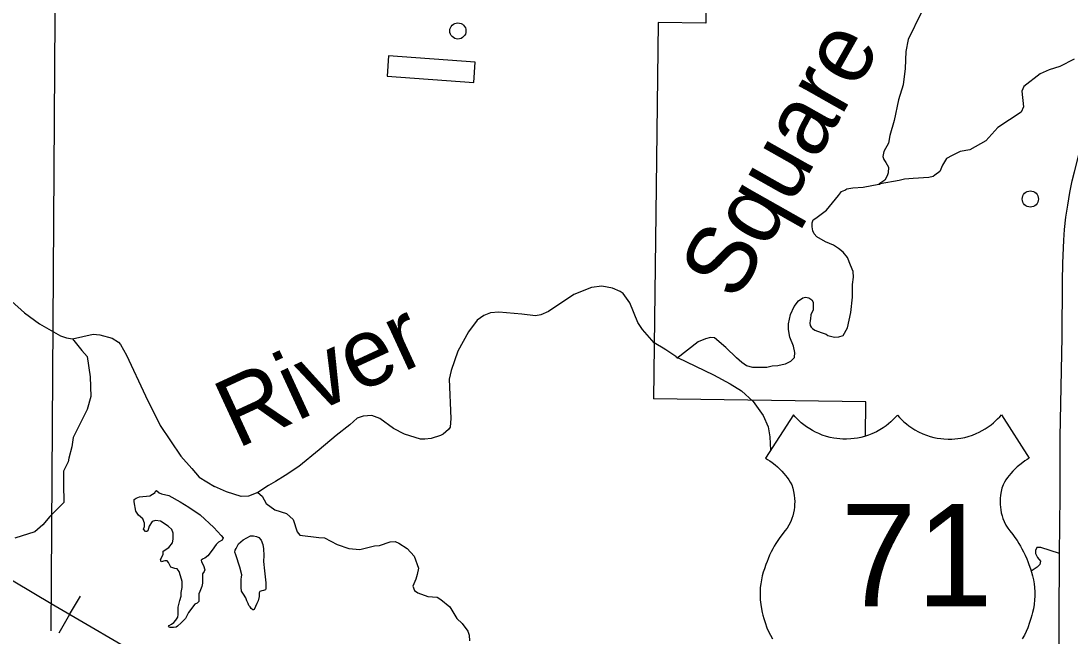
# Model space of a CAD drawing. Extents: x 1382482 to 1385815, y 1168351 to 1170484.
# Drawn here: x 1384071.2 to 1384330.9, y 1169323.8 to 1169475.9 of the extents above; entities that cross this region are included whole.
import ezdxf

# ---------------------------------------------------------------- set-up
doc = ezdxf.new("R2010")
doc.units = 0
for name, color, linetype in [('15', 7, 'Continuous'), ('22', 7, 'Continuous'), ('35', 7, 'Continuous'), ('4', 7, 'Continuous'), ('57', 7, 'Continuous'), ('6', 7, 'Continuous'), ('Default', 7, 'Continuous')]:
    doc.layers.add(name, color=color, linetype=linetype)

msp = doc.modelspace()

# ---------------------------------------------------------------- linework, layer by layer
at = {"layer": '15'}
msp.add_lwpolyline([(1384338.14, 1169311.22), (1384328.14, 1169311.27), (1384328.32, 1169344.04), (1384328.45, 1169358.54), (1384328.5, 1169373.03), (1384328.95, 1169397.67), (1384329.04, 1169411.52), (1384329.08, 1169416.04), (1384329.38, 1169421.73), (1384329.53, 1169424.34), (1384329.9, 1169427.4), (1384330.37, 1169430.41), (1384330.88, 1169433.52), (1384331.42, 1169436.43), (1384332, 1169438.62), (1384333.21, 1169443.46), (1384334.5, 1169447.58), (1384335.93, 1169451.66), (1384338.18, 1169457.24), (1384342.61, 1169467.31), (1384344.9, 1169472.5)], dxfattribs=at)
at = {"layer": '22'}
for points in [[(1384288.16, 1169378.43), (1384287.63, 1169377.84), (1384287.13, 1169377.32), (1384286.56, 1169376.79), (1384285.94, 1169376.26), (1384285.35, 1169375.8), (1384284.62, 1169375.29), (1384283.85, 1169374.81), (1384282.97, 1169374.32), (1384281.85, 1169373.8), (1384280.99, 1169373.47), (1384280.01, 1169373.15), (1384279.13, 1169372.92), (1384278.31, 1169372.75), (1384277.44, 1169372.62), (1384276.65, 1169372.54), (1384275.56, 1169372.49), (1384274.67, 1169372.5), (1384273.9, 1169372.54), (1384273.17, 1169372.62), (1384272.43, 1169372.73), (1384271.49, 1169372.92), (1384270.63, 1169373.15), (1384269.58, 1169373.49), (1384268.69, 1169373.84), (1384267.88, 1169374.22), (1384267.14, 1169374.6), (1384266.45, 1169375.01), (1384265.68, 1169375.51), (1384264.98, 1169376.02), (1384264.38, 1169376.52), (1384263.87, 1169376.97), (1384263.35, 1169377.47), (1384262.84, 1169378.01), (1384262.42, 1169378.49), (1384255.5, 1169367.78), (1384255.99, 1169367.48), (1384256.58, 1169367.1), (1384257.14, 1169366.7), (1384257.88, 1169366.12), (1384258.48, 1169365.61), (1384259.01, 1169365.12), (1384259.54, 1169364.58), (1384260.09, 1169363.96), (1384260.48, 1169363.49), (1384260.87, 1169362.99), (1384261.27, 1169362.44), (1384261.65, 1169361.86), (1384262, 1169361.18), (1384262.27, 1169360.34), (1384262.48, 1169359.52), (1384262.63, 1169358.63), (1384262.71, 1169357.81), (1384262.74, 1169357.02), (1384262.72, 1169356.28), (1384262.67, 1169355.68), (1384262.57, 1169354.95), (1384262.44, 1169354.27), (1384262.25, 1169353.53), (1384262.04, 1169352.87), (1384261.75, 1169352.14), (1384261.3, 1169351.2), (1384260.84, 1169350.46), (1384260.28, 1169349.79), (1384259.61, 1169348.92), (1384259.06, 1169348.16), (1384258.54, 1169347.39), (1384258.07, 1169346.65), (1384257.68, 1169345.97), (1384257.33, 1169345.35), (1384256.94, 1169344.6), (1384256.52, 1169343.73), (1384256.14, 1169342.87), (1384255.89, 1169342.23), (1384255.58, 1169341.42), (1384255.24, 1169340.42), (1384254.97, 1169339.59), (1384254.72, 1169338.69), (1384254.49, 1169337.64), (1384254.34, 1169336.7), (1384254.22, 1169335.73), (1384254.16, 1169334.66), (1384254.16, 1169333.66), (1384254.2, 1169332.68), (1384254.32, 1169331.53), (1384254.5, 1169330.45), (1384254.68, 1169329.62), (1384254.87, 1169328.9), (1384255.1, 1169328.08), (1384255.42, 1169327.07), (1384255.88, 1169325.83), (1384256.27, 1169324.92), (1384256.73, 1169323.99), (1384257.23, 1169323.08)], [(1384288.16, 1169378.43), (1384288.69, 1169377.84), (1384289.19, 1169377.32), (1384289.76, 1169376.79), (1384290.38, 1169376.26), (1384290.98, 1169375.8), (1384291.7, 1169375.29), (1384292.47, 1169374.81), (1384293.36, 1169374.32), (1384294.48, 1169373.8), (1384295.34, 1169373.47), (1384296.31, 1169373.15), (1384297.2, 1169372.92), (1384298.02, 1169372.75), (1384298.88, 1169372.62), (1384299.67, 1169372.54), (1384300.76, 1169372.49), (1384301.65, 1169372.5), (1384302.42, 1169372.54), (1384303.15, 1169372.62), (1384303.89, 1169372.73), (1384304.83, 1169372.92), (1384305.69, 1169373.15), (1384306.74, 1169373.49), (1384307.63, 1169373.84), (1384308.44, 1169374.22), (1384309.19, 1169374.6), (1384309.87, 1169375.01), (1384310.64, 1169375.51), (1384311.34, 1169376.02), (1384311.94, 1169376.52), (1384312.45, 1169376.97), (1384312.97, 1169377.47), (1384313.49, 1169378.01), (1384313.9, 1169378.49), (1384320.82, 1169367.78), (1384320.33, 1169367.48), (1384319.74, 1169367.1), (1384319.18, 1169366.7), (1384318.44, 1169366.12), (1384317.84, 1169365.61), (1384317.32, 1169365.12), (1384316.78, 1169364.58), (1384316.23, 1169363.96), (1384315.84, 1169363.49), (1384315.45, 1169362.99), (1384315.05, 1169362.44), (1384314.67, 1169361.86), (1384314.32, 1169361.18), (1384314.05, 1169360.34), (1384313.84, 1169359.52), (1384313.69, 1169358.63), (1384313.61, 1169357.81), (1384313.58, 1169357.02), (1384313.6, 1169356.28), (1384313.65, 1169355.68), (1384313.75, 1169354.95), (1384313.88, 1169354.27), (1384314.07, 1169353.53), (1384314.28, 1169352.87), (1384314.57, 1169352.14), (1384315.02, 1169351.2), (1384315.48, 1169350.46), (1384316.04, 1169349.79), (1384316.71, 1169348.92), (1384317.26, 1169348.16), (1384317.78, 1169347.39), (1384318.25, 1169346.65), (1384318.64, 1169345.97), (1384318.99, 1169345.35), (1384319.38, 1169344.6), (1384319.8, 1169343.73), (1384320.18, 1169342.87), (1384320.44, 1169342.23), (1384320.74, 1169341.42), (1384321.08, 1169340.42), (1384321.35, 1169339.59), (1384321.6, 1169338.69), (1384321.83, 1169337.64), (1384321.99, 1169336.7), (1384322.1, 1169335.73), (1384322.16, 1169334.66), (1384322.17, 1169333.66), (1384322.12, 1169332.68), (1384322, 1169331.53), (1384321.82, 1169330.45), (1384321.64, 1169329.62), (1384321.46, 1169328.9), (1384321.22, 1169328.08), (1384320.9, 1169327.07), (1384320.44, 1169325.83), (1384320.05, 1169324.92), (1384319.59, 1169323.99), (1384319.09, 1169323.08)]]:
    msp.add_lwpolyline(points, dxfattribs=at)
at = {"layer": '35'}
for p, q in [((1384262.73, 1169392.71), (1384262.73, 1169392.71)), ((1384263.22, 1169393.72), (1384263.22, 1169393.72))]:
    msp.add_line(p, q, dxfattribs=at)
for points in [[(1384294.03, 1169477.94), (1384290.84, 1169471.32), (1384290.27, 1169468.35), (1384290.05, 1169464.19), (1384289.6, 1169460.15), (1384288.43, 1169456.47), (1384287.38, 1169451.3), (1384286.29, 1169447.62), (1384285.99, 1169445.7), (1384284.79, 1169443.67), (1384284.53, 1169442.42), (1384284.82, 1169441.66), (1384285.33, 1169440.92), (1384285.93, 1169439.73)], [(1384331.95, 1169466.52), (1384328.35, 1169464.72), (1384325.72, 1169463.82), (1384323.47, 1169462.87), (1384319.5, 1169459.76), (1384318.97, 1169458.56), (1384319.35, 1169454.74), (1384318.82, 1169453.39), (1384313.03, 1169449.56), (1384310.03, 1169446.32), (1384306.09, 1169444.1), (1384303.7, 1169443.66), (1384301.71, 1169442.68), (1384300.32, 1169441.89), (1384299.31, 1169440.28), (1384298.63, 1169438.67), (1384297.47, 1169437.77), (1384297.02, 1169437.5), (1384295.97, 1169437.2), (1384292.07, 1169436.98), (1384289.91, 1169436.81), (1384288.59, 1169436.48), (1384283.89, 1169435.61)], [(1384285.93, 1169439.73), (1384285.85, 1169438.38), (1384285.66, 1169437.65), (1384285.04, 1169436.57), (1384283.58, 1169435.53)], [(1384262.73, 1169392.71), (1384262.76, 1169393.95), (1384262.41, 1169395.49), (1384261.52, 1169397.73), (1384261.18, 1169399.62), (1384261.18, 1169401.01), (1384261.68, 1169403.28), (1384262.64, 1169405.28), (1384263.72, 1169406.67), (1384264.76, 1169407.44), (1384265.45, 1169407.63), (1384266.26, 1169407.44), (1384266.99, 1169406.98), (1384267.34, 1169406.36), (1384267.34, 1169405.67), (1384267.3, 1169404.51), (1384266.76, 1169403.24), (1384266.65, 1169402.28), (1384266.57, 1169401.81), (1384266.45, 1169401.16), (1384266.57, 1169400.58), (1384266.8, 1169400.2), (1384267.15, 1169399.85), (1384267.69, 1169399.46), (1384269.3, 1169398.85), (1384270.5, 1169398.42), (1384270.96, 1169398.12), (1384272.58, 1169397.73), (1384273.7, 1169397.77), (1384274.74, 1169398.08), (1384275.78, 1169400), (1384276.66, 1169403.78), (1384277.01, 1169407.6), (1384277.09, 1169410.72), (1384277.28, 1169412.53), (1384277.2, 1169413.92), (1384276.59, 1169415.49), (1384275.78, 1169417.38), (1384274.74, 1169418.73), (1384273.62, 1169419.61), (1384272.35, 1169420.46), (1384270.34, 1169421.31), (1384268.23, 1169422.5), (1384267.57, 1169423.27), (1384267.22, 1169423.99), (1384267.03, 1169424.99), (1384267.07, 1169426.03), (1384267.34, 1169426.76), (1384267.99, 1169427.19), (1384270.61, 1169429.11), (1384273.62, 1169432.73), (1384274.35, 1169433.74), (1384275.12, 1169434.08), (1384275.68, 1169434.45), (1384277.11, 1169434.68), (1384279.73, 1169434.84), (1384283.58, 1169435.53), (1384283.86, 1169435.56), (1384283.89, 1169435.61)], [(1384042.2, 1169423.59), (1384050.89, 1169420.16), (1384057.39, 1169417.61), (1384059.78, 1169415.91), (1384063.8, 1169412.46), (1384068.87, 1169406.62), (1384072.09, 1169403.76), (1384075.79, 1169400.99), (1384080.97, 1169398.03), (1384082.46, 1169397.55), (1384083.93, 1169397.33), (1384089.09, 1169398.43), (1384090.76, 1169398.29), (1384093.8, 1169397.49), (1384095.31, 1169396.46), (1384095.87, 1169395.89), (1384097.31, 1169393.27), (1384102.03, 1169383.17), (1384105.64, 1169375.88), (1384110.75, 1169368.27), (1384113.52, 1169365.19), (1384115.33, 1169363.09), (1384119.13, 1169360.72)], [(1384217.61, 1169409.87), (1384214.97, 1169410.33), (1384212.46, 1169410.03), (1384208.09, 1169408.28), (1384201.81, 1169404.02), (1384199.93, 1169403.24), (1384198.54, 1169402.99), (1384195.21, 1169403.43), (1384189.46, 1169403.91), (1384187.4, 1169403.72), (1384185.76, 1169403.05), (1384184.12, 1169401.95), (1384181.98, 1169399.04), (1384179.33, 1169394.28), (1384177.7, 1169389.42), (1384177.19, 1169387.28), (1384177.6, 1169377.56), (1384177.46, 1169375.44), (1384177, 1169374.89), (1384175.75, 1169373.71), (1384175.05, 1169373.34), (1384172.77, 1169372.61), (1384171.19, 1169372.49), (1384170.11, 1169372.46), (1384166.15, 1169373.67), (1384163.44, 1169375.15), (1384160.06, 1169377.6), (1384158.05, 1169378.32), (1384155.93, 1169378.15), (1384154.46, 1169377.66), (1384152.65, 1169376.03), (1384149.27, 1169373.38), (1384144.99, 1169369.86), (1384139.99, 1169365.71), (1384136.6, 1169363.5), (1384134.21, 1169361.96), (1384132.47, 1169360.99), (1384129.87, 1169359.29), (1384127.57, 1169358.34), (1384125.73, 1169358.28), (1384122.1, 1169359.46), (1384119.13, 1169360.72)], [(1384233.32, 1169392.92), (1384230.58, 1169394.77), (1384227.94, 1169396.27), (1384225.05, 1169399.61), (1384223.88, 1169401.32), (1384221.9, 1169406.18), (1384220.25, 1169408.53), (1384219.57, 1169409.04), (1384217.61, 1169409.87)], [(1384083.93, 1169397.33), (1384086.31, 1169394.39), (1384087.56, 1169392.96), (1384088.33, 1169387.9), (1384088.48, 1169383), (1384087.59, 1169379.78), (1384084.09, 1169372.86), (1384083.83, 1169370.54), (1384083.05, 1169367.77), (1384082.91, 1169366.86), (1384081.77, 1169364.57), (1384081.75, 1169361.35), (1384081.82, 1169356.82), (1384079.58, 1169354.61), (1384078.36, 1169353.31), (1384076.6, 1169351.24), (1384074.61, 1169349.52), (1384069.68, 1169347.99)], [(1384262.73, 1169392.71), (1384261.73, 1169391.67), (1384260.38, 1169391.02), (1384258.59, 1169390.65), (1384257.19, 1169390.55), (1384255.88, 1169390.23), (1384252.39, 1169390.18), (1384250.85, 1169390.61), (1384249.69, 1169391.46), (1384248.35, 1169392.57), (1384245.69, 1169395.12), (1384242.91, 1169397.51), (1384241.91, 1169397.66), (1384240.65, 1169397.28), (1384238.86, 1169396.53), (1384233.59, 1169392.39)], [(1384230.58, 1169394.77), (1384230.78, 1169394.63)], [(1384233.32, 1169392.92), (1384233.71, 1169392.69), (1384242.61, 1169388.41), (1384246.77, 1169386.18), (1384249.54, 1169384.4), (1384252.47, 1169381.82), (1384254.9, 1169378.35), (1384256.2, 1169375.49), (1384256.55, 1169373.04), (1384256.79, 1169369.78)], [(1384110.88, 1169334.52), (1384111.1, 1169335.78), (1384111.1, 1169337.25), (1384110.66, 1169338.65), (1384110.36, 1169339.76), (1384109.85, 1169340.42), (1384109.26, 1169340.5), (1384108.3, 1169340.79), (1384107.71, 1169341.97), (1384107.41, 1169342.34), (1384106.82, 1169342.34), (1384105.87, 1169342.12), (1384105.72, 1169342.71), (1384106.38, 1169343.96), (1384106.38, 1169344.77), (1384107.78, 1169345.66), (1384108.74, 1169346.84), (1384108.89, 1169347.72), (1384108.89, 1169349.2), (1384108.52, 1169350.15), (1384107.64, 1169350.97), (1384105.72, 1169352.15), (1384104.5, 1169352.33), (1384103.66, 1169352.07), (1384102.92, 1169350.97), (1384102.62, 1169349.79), (1384102.33, 1169349.64), (1384102.03, 1169349.64), (1384101.52, 1169350.23), (1384101.81, 1169350.89), (1384101.81, 1169351.7), (1384101.37, 1169352.73), (1384100.26, 1169353.69), (1384099.68, 1169354.65), (1384099.23, 1169356.97), (1384099.23, 1169357.56), (1384099.71, 1169357.9), (1384100.56, 1169358.19), (1384103.07, 1169358.49), (1384104.39, 1169359.3), (1384104.54, 1169359.59), (1384104.76, 1169359.74), (1384105.42, 1169359.19), (1384106.01, 1169358.93), (1384107.78, 1169358.56)], [(1384107.78, 1169358.56), (1384110.61, 1169356.98), (1384112.79, 1169355.66), (1384115.59, 1169353.74), (1384118.94, 1169350.61), (1384120.75, 1169348.65), (1384121.23, 1169348.03), (1384121.04, 1169347.51), (1384120.12, 1169346.96), (1384119.53, 1169346.44), (1384118.54, 1169345), (1384117.47, 1169343.64), (1384116.69, 1169343.01), (1384116.33, 1169342.86), (1384115.85, 1169342.53), (1384115.92, 1169342.16), (1384116.36, 1169341.2), (1384116.69, 1169340.14), (1384116.55, 1169339.69), (1384116.18, 1169339.14), (1384116.18, 1169338.22), (1384116.18, 1169337.52), (1384116.18, 1169336.82), (1384115.99, 1169336.01), (1384115.52, 1169334.79), (1384115.22, 1169334.21), (1384115.22, 1169333.54), (1384115.26, 1169332.84), (1384115.26, 1169332.29), (1384114.85, 1169331.88), (1384114.26, 1169331.66), (1384112.68, 1169329.57), (1384111.94, 1169328.09), (1384110.83, 1169327.02), (1384109.99, 1169326.21), (1384109.66, 1169325.92), (1384108.99, 1169325.88), (1384108.44, 1169325.88), (1384108.11, 1169325.88), (1384107.89, 1169325.99), (1384107.74, 1169326.14), (1384107.92, 1169326.36), (1384108.44, 1169326.73), (1384109.03, 1169327.13), (1384109.54, 1169327.69), (1384110.02, 1169328.39), (1384110.1, 1169329.12), (1384110.13, 1169330.89), (1384110.54, 1169332.59), (1384110.83, 1169333.66), (1384110.88, 1169334.52)], [(1384129.87, 1169359.29), (1384130.91, 1169358.36), (1384131.88, 1169356.57), (1384134.05, 1169354.95), (1384136.92, 1169354.09), (1384138.56, 1169352.58), (1384139.58, 1169349.51), (1384140.22, 1169348.71), (1384144.98, 1169348.16), (1384146.37, 1169348.04), (1384149.51, 1169346.42), (1384152.34, 1169345.45), (1384155.06, 1169345.14), (1384158.7, 1169346.04), (1384159.97, 1169346.17), (1384162.6, 1169347.07), (1384163.83, 1169347.12), (1384164.75, 1169346.77), (1384166.83, 1169345.38), (1384168.56, 1169343.51), (1384169.63, 1169340.59), (1384169.32, 1169338.99), (1384168.95, 1169337.84), (1384168.21, 1169336.11), (1384168.65, 1169335), (1384169.41, 1169334.48), (1384171.89, 1169333.58), (1384174.24, 1169333.36), (1384175.12, 1169332.81), (1384177.4, 1169330.99), (1384179.14, 1169328.08), (1384180.42, 1169326.88), (1384181.83, 1169324.94), (1384182.19, 1169323.98), (1384182.2, 1169322.54)], [(1384125.87, 1169338.93), (1384125.36, 1169340.77), (1384124.4, 1169343.83), (1384124.14, 1169344.53), (1384124.21, 1169345.01), (1384124.51, 1169345.46), (1384125.02, 1169346.56), (1384126.17, 1169347.56), (1384128.05, 1169348.55), (1384128.75, 1169348.55), (1384129.48, 1169348.37), (1384130.07, 1169348.11), (1384130.63, 1169347.52), (1384131.1, 1169346.45), (1384131.22, 1169345.35), (1384131.29, 1169343.72), (1384131.22, 1169342.18)], [(1384328.32, 1169344.22), (1384323.64, 1169345.63), (1384322.71, 1169345.67), (1384322.33, 1169344.94), (1384322.33, 1169344.22), (1384322.82, 1169343.2), (1384323.63, 1169342.28), (1384323.43, 1169341.48), (1384322.8, 1169340.76), (1384321.28, 1169339.79)], [(1384131.22, 1169342.18), (1384131.47, 1169339.93), (1384131.84, 1169336.94), (1384131.84, 1169335.91), (1384131.84, 1169335.5), (1384131.73, 1169335.17), (1384131.22, 1169335.02), (1384130.81, 1169334.95), (1384130.37, 1169334.8), (1384130.15, 1169334.47), (1384130.15, 1169333.99), (1384130.15, 1169333.51), (1384129.96, 1169332.48), (1384129.59, 1169331.78), (1384129.26, 1169331.08), (1384128.93, 1169330.34), (1384128.78, 1169330.27), (1384128.6, 1169330.27), (1384128.16, 1169330.56), (1384127.94, 1169330.97), (1384127.6, 1169331.28), (1384127.46, 1169331.8), (1384127.09, 1169332.48), (1384126.9, 1169333.22), (1384126.28, 1169334.1), (1384125.83, 1169334.88), (1384125.69, 1169335.76), (1384125.69, 1169336.57), (1384125.69, 1169337.86), (1384125.83, 1169338.34), (1384125.87, 1169338.93)]]:
    msp.add_lwpolyline(points, dxfattribs=at)
at = {"layer": '4'}
msp.add_lwpolyline([(1384079.7, 1169497.67), (1384079.66, 1169490.52), (1384079.65, 1169489.69), (1384078.61, 1169325.02)], dxfattribs=at)
at = {"layer": '57'}
for p, q in [((1384162.21, 1169467.3), (1384161.84, 1169462.31)), ((1384183.65, 1169465.71), (1384162.21, 1169467.3)), ((1384183.28, 1169460.72), (1384183.65, 1169465.71)), ((1384161.84, 1169462.31), (1384183.28, 1169460.72))]:
    msp.add_line(p, q, dxfattribs=at)
at = {"layer": '6'}
for points in [[(1384281.73, 1169535.07), (1384281.47, 1169486.56), (1384240.92, 1169487.19), (1384240.77, 1169475.39), (1384228.97, 1169475.57), (1384228.46, 1169434.91), (1384227.8, 1169382.44)], [(1384280.29, 1169373.2), (1384280.38, 1169381.69), (1384227.8, 1169382.44)]]:
    msp.add_lwpolyline(points, dxfattribs=at)
at = {"layer": 'Default'}
for q in [(1384085.91, 1169333.6), (1384080.59, 1169324.49)]:
    msp.add_line((1384083.25, 1169329.05), q, dxfattribs=at)
for points in [[(1384332.09, 1169183.43), (1384316.13, 1169192.72), (1384311.91, 1169195.18), (1384294.47, 1169205.41), (1384281.57, 1169212.93), (1384249.18, 1169231.98), (1384225.57, 1169246.05), (1384170.06, 1169278.7), (1384103.85, 1169317.01), (1384078.66, 1169331.73), (1384060.2, 1169342.7), (1384005.02, 1169375.11), (1383961.45, 1169400.66), (1383910.1, 1169431.23), (1383873.88, 1169452.49), (1383841.86, 1169471.32), (1383837.41, 1169474.46), (1383834.73, 1169476.33)], [(1384332.09, 1169183.43), (1384316.13, 1169192.72), (1384311.91, 1169195.18), (1384294.47, 1169205.41), (1384281.57, 1169212.93), (1384249.18, 1169231.98), (1384225.57, 1169246.05), (1384170.06, 1169278.7), (1384103.85, 1169317.01), (1384078.66, 1169331.73), (1384060.2, 1169342.7), (1384005.02, 1169375.11), (1383961.45, 1169400.66), (1383910.1, 1169431.23), (1383873.88, 1169452.49), (1383841.86, 1169471.32)]]:
    msp.add_lwpolyline(points, dxfattribs=at)
for centre in [(1384179.37, 1169473.48), (1384321.07, 1169431.89)]:
    msp.add_circle(centre, 2, dxfattribs=at)

# ---------------------------------------------------------------- texts
at = {"layer": '22'}
msp.add_text('71', height=25.344, dxfattribs=at).set_placement((1384274.09, 1169331.11))
at = {"layer": '35'}
for s, rotation, p in [('Square', 60.549, (1384248.3, 1169406.2)), ('River', 24.7862, (1384124.69, 1169370.02))]:
    msp.add_text(s, height=16.896, rotation=rotation, dxfattribs=at).set_placement(p)

doc.saveas('drawing.dxf')
